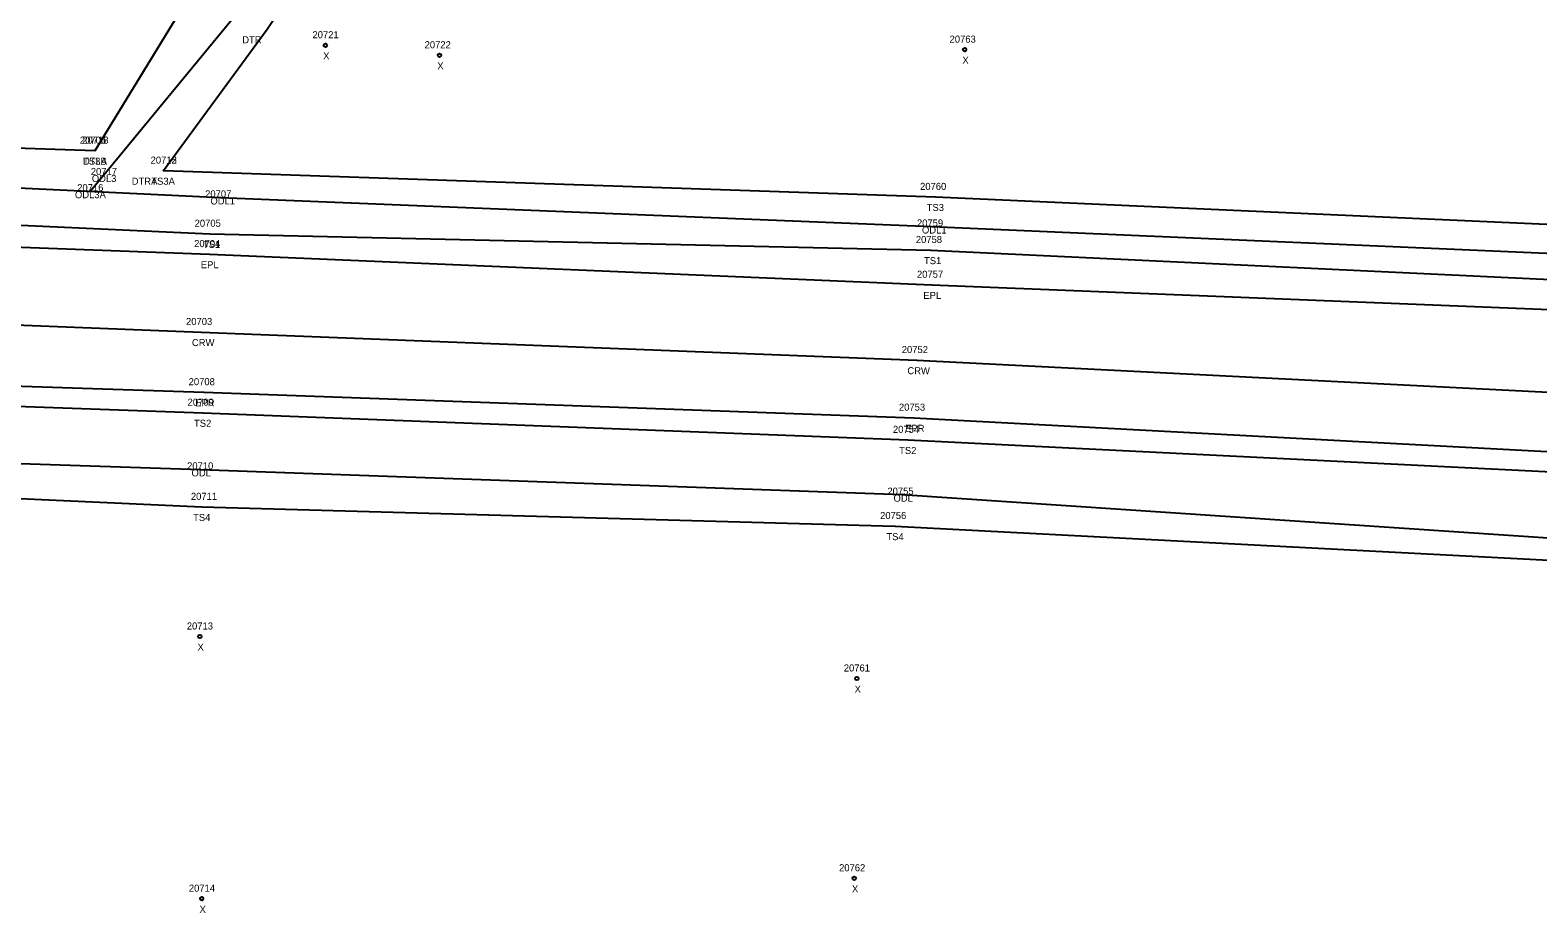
# Model space of a CAD drawing. Extents: x 1966740 to 1969291, y 1117378 to 1118461.
# Drawn here: x 1968863.2 to 1969077.2, y 1117818 to 1117943.2 of the extents above; entities that cross this region are included whole.
import ezdxf

# ---------------------------------------------------------------- set-up
doc = ezdxf.new("R2010")
doc.units = 0
for name, color, linetype in [('RD_DTM_BkLn1', 7, 'Continuous'), ('RD_DTM_BkLn2', 7, 'Continuous'), ('RD_EX_H2O', 7, 'Continuous'), ('RD_EX_H2O_txCode', 7, 'Continuous'), ('RD_EX_Road', 7, 'Continuous'), ('RD_EX_Road_txCode', 7, 'Continuous'), ('RD_SMD_Locator', 7, 'Continuous'), ('RD_SMD_Misc', 7, 'Continuous')]:
    doc.layers.add(name, color=color, linetype=linetype)

msp = doc.modelspace()

# ---------------------------------------------------------------- linework, layer by layer
at = {"layer": 'RD_DTM_BkLn1'}
msp.add_lwpolyline([(1968529.36, 1117916.3), (1968681.48, 1117908.5), (1968781.89, 1117904.51), (1968887.49, 1117900.39), (1968989.06, 1117896.4), (1969090.87, 1117891.24), (1969190.23, 1117887.94), (1969284.4, 1117884.73)], dxfattribs=at)
at = {"layer": 'RD_DTM_BkLn2'}
for points in [[(1968532.27, 1117940.77), (1968682.68, 1117932.75), (1968784.38, 1117929.07), (1968872.44, 1117926.13)], [(1968531.49, 1117931.42), (1968682.06, 1117924.3), (1968783.42, 1117919.17), (1968888.7, 1117914.33), (1968991.06, 1117912.02), (1969093.07, 1117907.16), (1969191.83, 1117902.92), (1969283.72, 1117899.63)], [(1968882.13, 1117923.29), (1968991.72, 1117919.56), (1969094.35, 1117914.97), (1969192.08, 1117910.66), (1969282.99, 1117908.48)], [(1968528.99, 1117899.6), (1968680.45, 1117894.84), (1968781.74, 1117892.71), (1968887.7, 1117888.94), (1968987.81, 1117885.08), (1969089.75, 1117880.01), (1969189.02, 1117876.39), (1969282.76, 1117873.05)], [(1968528.68, 1117880.51), (1968680.3, 1117884.55), (1968781.05, 1117880.46), (1968887.57, 1117875.57), (1968986, 1117872.85), (1969087.95, 1117867.56), (1969189.32, 1117864.4), (1969289.73, 1117862.33)]]:
    msp.add_lwpolyline(points, dxfattribs=at)
at = {"layer": 'RD_EX_H2O'}
for points in [[(1968872.44, 1117926.13), (1968885.78, 1117948), (1968904.93, 1117971.61), (1968923.41, 1117996.78), (1968940.56, 1118022.16)], [(1968871.74, 1117920.38), (1968873.64, 1117922.68), (1968893.41, 1117946.64), (1968909.65, 1117969.6), (1968926.07, 1117994.82), (1968943.8, 1118019.85)], [(1968882.13, 1117923.29), (1968896.84, 1117943.36), (1968912.83, 1117967.16), (1968928.85, 1117993.17), (1968947.1, 1118017.99)], [(1968531.76, 1117937.18), (1968682.22, 1117928.11), (1968784.28, 1117924.56), (1968890.2, 1117919.49), (1968991.22, 1117915.37), (1969093.76, 1117910.9), (1969192.08, 1117906.24), (1969283.24, 1117903.06)], [(1968528.55, 1117888.35), (1968679.78, 1117887.39), (1968780.67, 1117884.45), (1968887.36, 1117880.9), (1968987.02, 1117877.31), (1969088.58, 1117870.53), (1969189.53, 1117868.6), (1969284.94, 1117865.64)]]:
    msp.add_lwpolyline(points, dxfattribs=at)
at = {"layer": 'RD_EX_Road'}
for points in [[(1968530.54, 1117925.7), (1968681.97, 1117919.01), (1968783.23, 1117915.36), (1968888.64, 1117911.44), (1968991.22, 1117907.09), (1969091.98, 1117903.06), (1969191.09, 1117898.66), (1969283.27, 1117895.43)], [(1968527.82, 1117906.41), (1968680.79, 1117899.07), (1968781.71, 1117895.37), (1968887.86, 1117891.84), (1968988.65, 1117888.23), (1969090.1, 1117882.83), (1969189.3, 1117879.04), (1969282.94, 1117875.42)]]:
    msp.add_lwpolyline(points, dxfattribs=at)
at = {"layer": 'RD_SMD_Locator'}
for centre, radius in [((1968905.11, 1117941.08), 0.25), ((1968995.87, 1117940.46), 0.25), ((1968921.32, 1117939.66), 0.25), ((1968872.44, 1117926.13), 0.001), ((1968872.44, 1117926.13), 0.001), ((1968882.13, 1117923.29), 0.001), ((1968882.13, 1117923.29), 0.001), ((1968873.64, 1117922.68), 0.001), ((1968871.74, 1117920.38), 0.001), ((1968890.2, 1117919.49), 0.001), ((1968991.72, 1117919.56), 0.001), ((1968888.7, 1117914.33), 0.001), ((1968991.22, 1117915.37), 0.001), ((1968888.64, 1117911.44), 0.001), ((1968991.06, 1117912.02), 0.001), ((1968991.22, 1117907.09), 0.001), ((1968887.49, 1117900.39), 0.001), ((1968989.06, 1117896.4), 0.001), ((1968887.86, 1117891.84), 0.001), ((1968887.7, 1117888.94), 0.001), ((1968988.65, 1117888.23), 0.001), ((1968987.81, 1117885.08), 0.001), ((1968887.36, 1117880.9), 0.001), ((1968987.02, 1117877.31), 0.001), ((1968887.57, 1117875.57), 0.001), ((1968986, 1117872.85), 0.001), ((1968887.28, 1117857.17), 0.25), ((1968980.57, 1117851.21), 0.25), ((1968980.18, 1117822.86), 0.25), ((1968887.56, 1117819.96), 0.25)]:
    msp.add_circle(centre, radius, dxfattribs=at)

# ---------------------------------------------------------------- texts
at = {"layer": 'RD_EX_H2O_txCode'}
for s, p in [('DTR', (1968893.31, 1117941.36)), ('20718', (1968870.6, 1117927.13)), ('DTLA', (1968870.7, 1117924.13)), ('20715', (1968880.3, 1117924.29)), ('20717', (1968871.81, 1117922.68)), ('20716', (1968869.88, 1117920.38)), ('ODL3', (1968871.95, 1117921.68)), ('DTRA', (1968877.62, 1117921.29)), ('ODL3A', (1968869.56, 1117919.38)), ('20707', (1968888.04, 1117919.49)), ('ODL1', (1968888.79, 1117918.49)), ('20759', (1968989.1, 1117915.37)), ('ODL1', (1968989.81, 1117914.37)), ('20710', (1968885.48, 1117880.9)), ('ODL', (1968886.11, 1117879.9)), ('20755', (1968984.9, 1117877.31)), ('ODL', (1968985.77, 1117876.31))]:
    msp.add_text(s, height=1, dxfattribs=at).set_placement(p)
at = {"layer": 'RD_EX_Road_txCode'}
for s, p in [('20704', (1968886.48, 1117912.44)), ('EPL', (1968887.43, 1117909.44)), ('20757', (1968989.1, 1117908.09)), ('EPL', (1968990.01, 1117905.09)), ('20708', (1968885.7, 1117892.84)), ('EPR', (1968886.63, 1117889.84)), ('20753', (1968986.54, 1117889.23)), ('EPR', (1968987.42, 1117886.23))]:
    msp.add_text(s, height=1, dxfattribs=at).set_placement(p)
at = {"layer": 'RD_SMD_Misc'}
for s, p in [('20721', (1968903.28, 1117942.08)), ('20763', (1968993.73, 1117941.46)), ('X', (1968904.8, 1117939.08)), ('20722', (1968919.2, 1117940.66)), ('X', (1968921, 1117937.66)), ('X', (1968995.55, 1117938.46)), ('20706', (1968870.26, 1117927.13)), ('TS3B', (1968870.72, 1117924.13)), ('20712', (1968880.3, 1117924.29)), ('TS3A', (1968880.4, 1117921.29)), ('20760', (1968989.54, 1117920.56)), ('TS3', (1968990.48, 1117917.56)), ('20705', (1968886.55, 1117915.33)), ('TS1', (1968887.74, 1117912.33)), ('20758', (1968988.94, 1117913.02)), ('TS1', (1968990.1, 1117910.02)), ('20703', (1968885.33, 1117901.39)), ('CRW', (1968886.17, 1117898.39)), ('20752', (1968986.94, 1117897.4)), ('CRW', (1968987.74, 1117894.4)), ('20709', (1968885.55, 1117889.94)), ('TS2', (1968886.46, 1117886.94)), ('20754', (1968985.69, 1117886.08)), ('TS2', (1968986.57, 1117883.08)), ('20711', (1968886.02, 1117876.57)), ('TS4', (1968886.33, 1117873.57)), ('20756', (1968983.86, 1117873.85)), ('TS4', (1968984.76, 1117870.85)), ('20713', (1968885.44, 1117858.17)), ('X', (1968886.96, 1117855.17)), ('20761', (1968978.71, 1117852.21)), ('X', (1968980.25, 1117849.21)), ('20762', (1968978.04, 1117823.86)), ('20714', (1968885.73, 1117820.96)), ('X', (1968979.87, 1117820.86)), ('X', (1968887.25, 1117817.96))]:
    msp.add_text(s, height=1, dxfattribs=at).set_placement(p)

doc.saveas('drawing.dxf')
